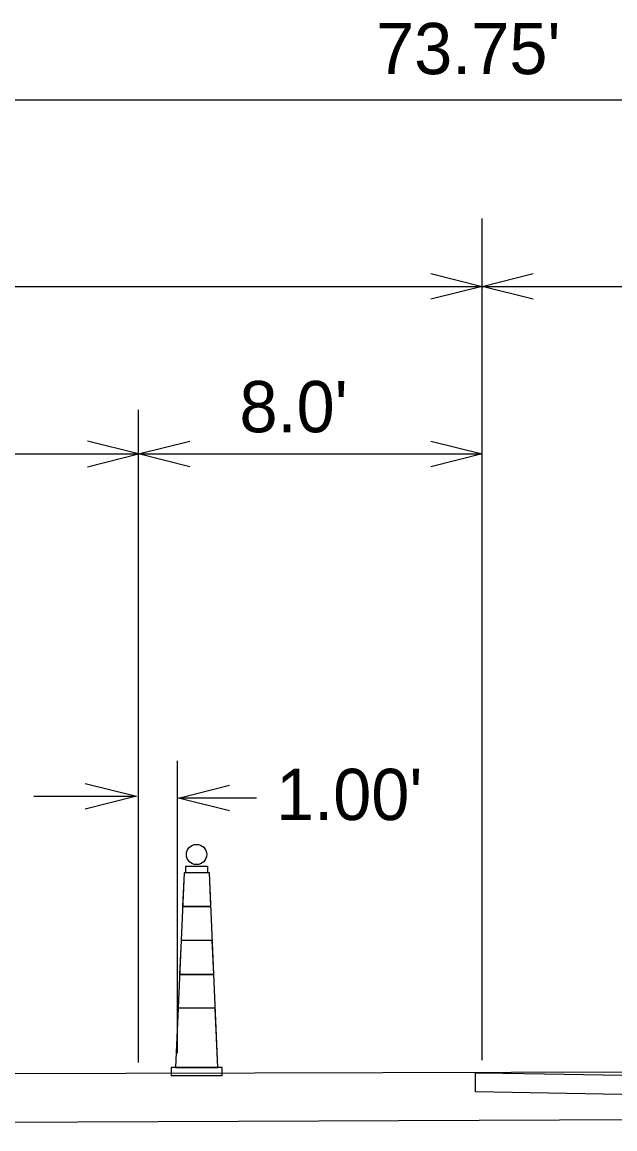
# Model space of a CAD drawing. Extents: x 8771 to 81668, y 6145 to 11018.
# Drawn here: x 11468.9 to 11731.7, y 6163.7 to 6654.1 of the extents above; entities that cross this region are included whole.
import ezdxf

# ---------------------------------------------------------------- set-up
doc = ezdxf.new("R2010")
doc.units = 0
for name, color, linetype in [('dsnCellElements', 7, 'Continuous'), ('Level 8', 7, 'Continuous'), ('ShtPlotIdentification', 7, 'Continuous')]:
    doc.layers.add(name, color=color, linetype=linetype)

msp = doc.modelspace()

# ---------------------------------------------------------------- linework, layer by layer
at = {"layer": 'dsnCellElements'}
for p, q in [((10720.67, 6619.67), (12624.93, 6619.67)), ((11672.8, 6194.09), (11672.8, 6567.12)), ((10720.67, 6536.96), (11672.8, 6536.96)), ((10879.42, 6536.96), (11672.8, 6536.96)), ((11672.8, 6536.96), (12624.93, 6536.96)), ((11520.54, 6193.1), (11520.54, 6482.26)), ((11295.04, 6462.74), (11672.8, 6462.74)), ((11537.75, 6197.32), (11537.75, 6326.74)), ((11474.13, 6311.06), (11519.54, 6311.06)), ((11572.86, 6310.28), (11538.17, 6310.28)), ((10779.45, 6163.72), (11752.89, 6167.9))]:
    msp.add_line(p, q, dxfattribs=at)
for points in [[(11650.09, 6542.63), (11672.8, 6536.96), (11650.09, 6531.28)], [(11695.51, 6531.28), (11672.8, 6536.96), (11695.51, 6542.63)], [(11497.83, 6457.06), (11520.54, 6462.74), (11497.83, 6468.42)], [(11543.25, 6457.06), (11520.54, 6462.74), (11543.25, 6468.42)], [(11650.09, 6468.42), (11672.8, 6462.74), (11650.09, 6457.06)], [(11496.84, 6316.73), (11519.54, 6311.06), (11496.84, 6305.38)], [(11560.88, 6304.6), (11538.17, 6310.28), (11560.88, 6315.96)]]:
    msp.add_lwpolyline(points, dxfattribs=at)
at = {"layer": 'Level 8'}
for p, q in [((11540.67, 6277.18), (11536.92, 6190.93)), ((11540.67, 6277.18), (11540.02, 6262.18)), ((11551.92, 6277.18), (11540.67, 6277.18)), ((11551.92, 6277.18), (11540.67, 6277.18)), ((11555.67, 6190.93), (11551.92, 6277.18)), ((11552.57, 6262.18), (11551.92, 6277.18)), ((11552.57, 6262.18), (11540.02, 6262.18)), ((11540.02, 6262.18), (11552.57, 6262.18)), ((11539.37, 6247.18), (11538.71, 6232.18)), ((11553.22, 6247.18), (11539.37, 6247.18)), ((11553.22, 6247.18), (11539.37, 6247.18)), ((11553.88, 6232.18), (11553.22, 6247.18)), ((11553.88, 6232.18), (11538.71, 6232.18)), ((11538.71, 6232.18), (11553.88, 6232.18)), ((11538.06, 6217.18), (11536.92, 6190.93)), ((11554.53, 6217.18), (11538.06, 6217.18)), ((11554.53, 6217.18), (11538.06, 6217.18)), ((11555.67, 6190.93), (11554.53, 6217.18)), ((11557.54, 6190.93), (11535.04, 6190.93)), ((11535.04, 6190.93), (11535.04, 6187.18)), ((11536.92, 6190.93), (11555.67, 6190.93)), ((11557.54, 6187.18), (11557.54, 6190.93)), ((11557.54, 6187.18), (11535.04, 6187.18))]:
    msp.add_line(p, q, dxfattribs=at)
msp.add_lwpolyline([(11541.42, 6280.18), (11551.02, 6280.18), (11551.02, 6277.18), (11541.42, 6277.18)], close=True, dxfattribs=at)
msp.add_circle((11546.22, 6285.28), 4.5, dxfattribs=at)
at = {"layer": 'ShtPlotIdentification'}
for p, q in [((11752.89, 6188.81), (10720.67, 6186.12)), ((11669.91, 6180.13), (11669.92, 6184.61)), ((12100.92, 6172.61), (11669.91, 6180.13))]:
    msp.add_line(p, q, dxfattribs=at)
msp.add_lwpolyline([(11669.92, 6184.61), (11669.95, 6188.59), (11681.96, 6188.39), (11700.48, 6188.07), (11726.48, 6187.63), (11759.21, 6187.07), (11806.37, 6186.26), (11871.61, 6185.15), (11906.06, 6184.56), (12103.22, 6181.19)], dxfattribs=at)

# ---------------------------------------------------------------- texts
at = {"layer": 'dsnCellElements'}
for s, p in [("73.75'", (11625.82, 6631.02)), ("8.0'", (11565.25, 6472.36)), ("1.00'", (11581.49, 6300.53))]:
    msp.add_text(s, height=22.709, dxfattribs=at).set_placement(p)

doc.saveas('drawing.dxf')
